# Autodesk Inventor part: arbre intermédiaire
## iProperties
Shininess: 64.0
Length Units: 11269
Angle Units: 11279
Time Units: 11290
Mass Units: 11283
Length Display Precision: 3
Angle Display Precision: 2
Compacted: True
Part Number: arbre intermédiaire
Document SubType Name: Modeling
Created: 2004-09
Material: Par défaut
Designer: Laurent
Density: 1 g/cm^3
Density: 0.0
Volumn: 0.0
Area: 0.0
PropertySet Name: Model Information
Control State: 0
Master: False
Checked Out: False
Author: Laurent
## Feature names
1. Extrusion1
2. Extrusion2
3. Extrusion3
4. Extrusion4
5. Extrusion5
6. Extrusion6
7. Chanfrein1 [Chamfer]
8. Congé1 [Fillet]
